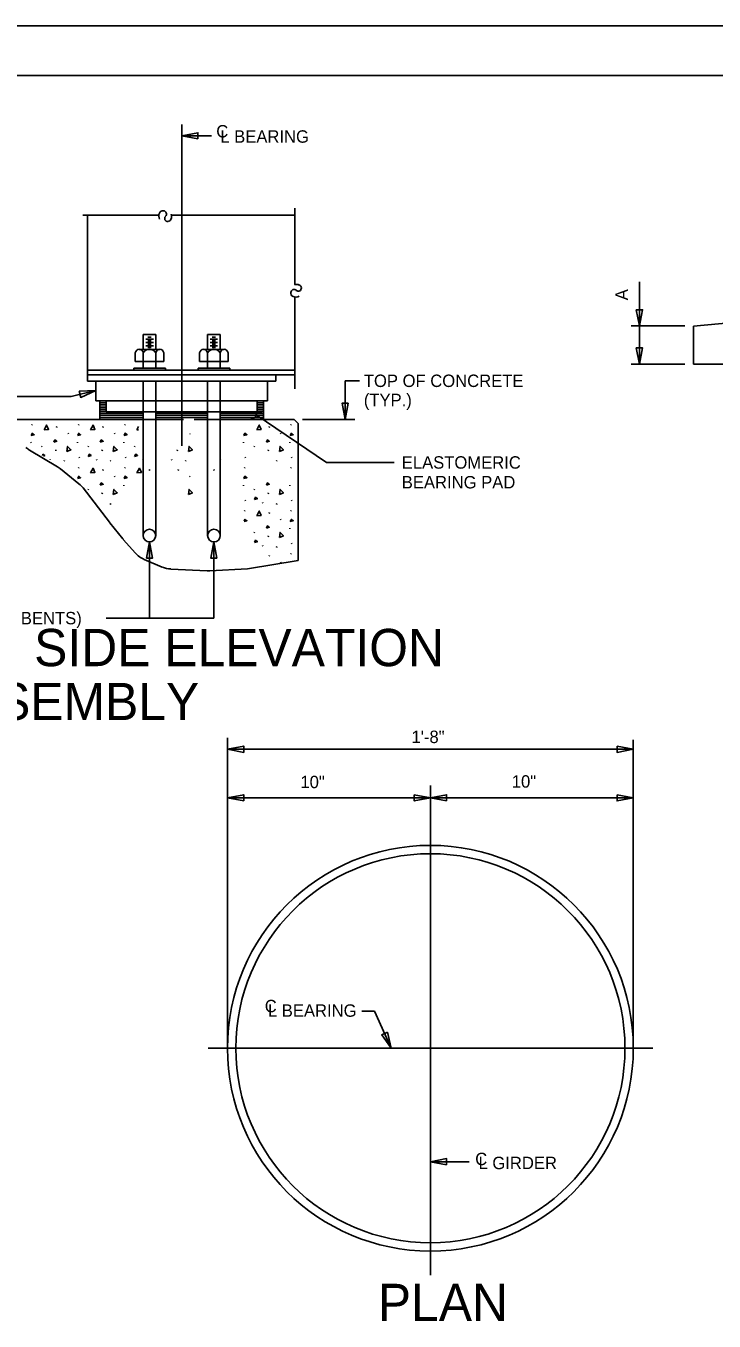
# Model space of a CAD drawing. Extents: x -125.5 to -89.4, y -5.1 to 16.9.
# Drawn here: x -112.46 to -105.53, y 3.9 to 16.93 of the extents above; entities that cross this region are included whole.
import ezdxf

# ---------------------------------------------------------------- set-up
doc = ezdxf.new("R2010")
doc.units = 0
for name, color, linetype in [('BR_AUTO DIMENSION', 7, 'Continuous'), ('BR_BORDER LINES', 7, 'Continuous'), ('BR_CENTER LINES', 7, 'Continuous'), ('BR_CONCRETE', 7, 'Continuous'), ('BR_REBAR', 7, 'Continuous'), ('BR_STRUCTURAL STEEL', 7, 'Continuous'), ('BR_TEXT', 7, 'Continuous'), ('Default', 7, 'Continuous'), ('Level 31', 7, 'Continuous')]:
    doc.layers.add(name, color=color, linetype=linetype)

msp = doc.modelspace()

# ---------------------------------------------------------------- linework, layer by layer
at = {"layer": 'BR_AUTO DIMENSION'}
for p, q in [((-110.889, 15.827), (-110.588, 15.827)), ((-106.282, 13.53), (-106.282, 14.357)), ((-106.365, 13.914), (-105.826, 13.914)), ((-106.365, 13.53), (-105.826, 13.53)), ((-109.244, 12.973), (-109.244, 13.36)), ((-109.244, 13.36), (-109.1, 13.36)), ((-112.001, 13.204), (-112.841, 13.204)), ((-111.755, 13.264), (-112.001, 13.204)), ((-110.139, 13.018), (-109.432, 12.538)), ((-109.674, 12.973), (-109.147, 12.973)), ((-109.432, 12.538), (-108.749, 12.538)), ((-111.213, 11.74), (-111.213, 10.973)), ((-110.565, 11.74), (-110.565, 10.973)), ((-110.565, 10.973), (-111.648, 10.973)), ((-110.428, 7.085), (-110.428, 9.766)), ((-110.428, 9.653), (-106.344, 9.653)), ((-106.344, 7.085), (-106.344, 9.749)), ((-110.428, 9.163), (-106.344, 9.163)), ((-110.428, 6.643), (-110.428, 8.478)), ((-106.344, 6.643), (-106.344, 8.478)), ((-109.075, 7.015), (-108.949, 7.015)), ((-108.949, 7.015), (-108.78, 6.643)), ((-108.386, 5.501), (-107.996, 5.501))]:
    msp.add_line(p, q, dxfattribs=at)
for points in [[(-110.726, 15.796), (-110.889, 15.827), (-110.726, 15.858)], [(-106.314, 14.077), (-106.282, 13.914), (-106.251, 14.077)], [(-106.314, 13.693), (-106.282, 13.53), (-106.251, 13.693)], [(-111.919, 13.256), (-111.754, 13.264), (-111.905, 13.195)], [(-109.213, 13.135), (-109.244, 12.973), (-109.275, 13.135)], [(-111.244, 11.577), (-111.213, 11.739), (-111.181, 11.577)], [(-110.534, 11.577), (-110.565, 11.739), (-110.596, 11.577)], [(-110.265, 9.621), (-110.428, 9.653), (-110.265, 9.684)], [(-106.507, 9.684), (-106.344, 9.653), (-106.507, 9.621)], [(-110.265, 9.132), (-110.428, 9.163), (-110.265, 9.194)], [(-108.549, 9.194), (-108.386, 9.163), (-108.549, 9.132)], [(-108.224, 9.132), (-108.386, 9.163), (-108.224, 9.194)], [(-106.507, 9.194), (-106.344, 9.163), (-106.507, 9.132)], [(-108.819, 6.804), (-108.78, 6.643), (-108.876, 6.778)], [(-108.224, 5.47), (-108.386, 5.501), (-108.224, 5.532)]]:
    msp.add_lwpolyline(points, close=True, dxfattribs=at)
for centre, start, end in [((-110.103, 13.015), 53.0627, 175.5269), ((-110.176, 13.021), 233.0627, 355.5269)]:
    msp.add_arc(centre, 0.0366, start, end, dxfattribs=at)
at = {"layer": 'BR_BORDER LINES'}
msp.add_line((-90.033, 16.434), (-123.699, 16.434), dxfattribs=at)
at = {"layer": 'BR_CENTER LINES'}
for p, q in [((-110.889, 15.941), (-110.889, 12.708)), ((-108.386, 4.359), (-108.386, 9.288)), ((-110.622, 6.643), (-106.147, 6.643))]:
    msp.add_line(p, q, dxfattribs=at)
at = {"layer": 'BR_CONCRETE'}
for p, q in [((-110.915, 12.973), (-112.775, 12.973)), ((-111.629, 12.973), (-110.871, 12.973)), ((-109.758, 12.973), (-110.762, 12.973)), ((-109.758, 12.973), (-109.716, 12.931)), ((-109.716, 11.551), (-109.716, 12.931))]:
    msp.add_line(p, q, dxfattribs=at)
at = {"layer": 'BR_REBAR'}
for p, q in [((-111.276, 13.827), (-111.149, 13.827)), ((-111.276, 13.678), (-111.276, 13.827)), ((-111.149, 13.678), (-111.149, 13.827)), ((-110.502, 13.827), (-110.629, 13.827)), ((-110.629, 13.678), (-110.629, 13.827)), ((-110.502, 13.678), (-110.502, 13.827)), ((-111.251, 13.782), (-111.174, 13.782)), ((-111.251, 13.748), (-111.174, 13.748)), ((-111.251, 13.713), (-111.174, 13.713)), ((-111.229, 13.8), (-111.197, 13.8)), ((-111.229, 13.765), (-111.197, 13.765)), ((-111.229, 13.73), (-111.197, 13.73)), ((-111.229, 13.696), (-111.197, 13.696)), ((-110.527, 13.782), (-110.603, 13.782)), ((-110.527, 13.748), (-110.603, 13.748)), ((-110.527, 13.713), (-110.603, 13.713)), ((-110.549, 13.8), (-110.581, 13.8)), ((-110.549, 13.765), (-110.581, 13.765)), ((-110.549, 13.73), (-110.581, 13.73)), ((-110.549, 13.696), (-110.581, 13.696)), ((-111.356, 13.644), (-111.356, 13.557)), ((-111.316, 13.678), (-111.109, 13.678)), ((-111.276, 13.488), (-111.276, 13.644)), ((-111.149, 13.488), (-111.149, 13.644)), ((-111.069, 13.644), (-111.069, 13.557)), ((-110.709, 13.644), (-110.709, 13.557)), ((-110.462, 13.678), (-110.669, 13.678)), ((-110.629, 13.488), (-110.629, 13.644)), ((-110.502, 13.488), (-110.502, 13.644)), ((-110.422, 13.644), (-110.422, 13.557)), ((-111.372, 13.488), (-111.372, 13.47)), ((-111.372, 13.488), (-111.053, 13.488)), ((-111.069, 13.557), (-111.356, 13.557)), ((-111.053, 13.488), (-111.053, 13.47)), ((-110.724, 13.488), (-110.724, 13.47)), ((-110.406, 13.488), (-110.724, 13.488)), ((-110.709, 13.557), (-110.422, 13.557)), ((-110.406, 13.488), (-110.406, 13.47)), ((-111.276, 13.15), (-111.276, 13.358)), ((-111.149, 13.15), (-111.149, 13.358)), ((-110.629, 13.15), (-110.629, 13.358)), ((-110.502, 13.15), (-110.502, 13.358)), ((-111.276, 12.962), (-111.276, 13.16)), ((-111.149, 12.962), (-111.149, 13.16)), ((-110.629, 12.962), (-110.629, 13.16)), ((-110.502, 12.962), (-110.502, 13.16)), ((-111.276, 11.804), (-111.276, 12.962)), ((-111.149, 11.804), (-111.149, 12.962)), ((-110.629, 11.804), (-110.629, 12.962)), ((-110.502, 11.804), (-110.502, 12.962))]:
    msp.add_line(p, q, dxfattribs=at)
for centre in [(-111.213, 11.804), (-110.565, 11.804)]:
    msp.add_circle(centre, 0.0637, dxfattribs=at)
for centre, major_axis, start_param, end_param in [((-111.316, 13.634), (0, 0.0444), 4.933703, 7.632667), ((-111.213, 13.592), (0, 0.0867), 5.35589, 7.210481), ((-111.109, 13.634), (0, 0.0444), 4.933703, 7.632667), ((-110.669, 13.634), (0, 0.0444), 4.933703, 7.632667), ((-110.565, 13.592), (0, 0.0867), 5.35589, 7.210481), ((-110.462, 13.634), (0, 0.0444), 4.933703, 7.632667)]:
    msp.add_ellipse(centre, major_axis=major_axis, ratio=0.918783, start_param=start_param, end_param=end_param, dxfattribs=at)
at = {"layer": 'BR_STRUCTURAL STEEL'}
for p, q in [((-111.837, 15.028), (-111.837, 13.42)), ((-101.906, 14.291), (-105.739, 13.91)), ((-105.739, 13.91), (-105.739, 13.53)), ((-111.837, 13.47), (-109.75, 13.47)), ((-101.906, 13.53), (-105.739, 13.53)), ((-111.837, 13.42), (-110.588, 13.42)), ((-111.837, 13.42), (-111.837, 13.358)), ((-111.837, 13.358), (-109.941, 13.358)), ((-111.754, 13.358), (-111.754, 13.16)), ((-111.372, 13.358), (-111.053, 13.358)), ((-110.588, 13.42), (-109.75, 13.42)), ((-110.024, 13.358), (-110.024, 13.16)), ((-109.941, 13.42), (-109.941, 13.358)), ((-111.754, 13.16), (-110.024, 13.16)), ((-111.713, 13.16), (-111.713, 12.973)), ((-111.648, 13.049), (-111.648, 13.16)), ((-111.648, 13.049), (-110.13, 13.049)), ((-110.13, 13.049), (-110.13, 13.16)), ((-110.065, 13.16), (-110.065, 12.973))]:
    msp.add_line(p, q, dxfattribs=at)
for radius in [2.042, 1.958]:
    msp.add_circle((-108.386, 6.643), radius, dxfattribs=at)
at = {"layer": 'BR_TEXT'}
for p, q in [((-111.885, 15.028), (-111.119, 15.028)), ((-110.993, 15.028), (-109.75, 15.028)), ((-109.75, 14.331), (-109.75, 15.099)), ((-109.75, 13.282), (-109.75, 14.205))]:
    msp.add_line(p, q, dxfattribs=at)
for centre, radius, start, end in [((-111.049, 15.021), 0.0705, 155.6187, 208.3414), ((-111.077, 15.034), 0.0399, 83.2422, 155.6187), ((-111.076, 15.04), 0.0334, 316.8236, 83.2422), ((-111.03, 14.996), 0.0304, 136.8236, 275.5224), ((-111.061, 15.016), 0.07, 335.6333, 17.6449), ((-111.03, 15.002), 0.0358, 275.5224, 335.6333), ((-109.758, 14.248), 0.0334, 46.8235, 173.2422), ((-109.752, 14.247), 0.0399, 173.2422, 245.6187), ((-109.739, 14.275), 0.0705, 245.6187, 298.3414), ((-109.734, 14.262), 0.07, 65.6333, 107.6449), ((-109.715, 14.294), 0.0304, 226.8236, 5.5224), ((-109.72, 14.294), 0.0358, 5.5224, 65.6333)]:
    msp.add_arc(centre, radius, start, end, dxfattribs=at)
at = {"layer": 'Default'}
for p, q in [((-111.713, 13.139), (-111.648, 13.139)), ((-111.713, 13.118), (-111.648, 13.118)), ((-111.713, 13.097), (-111.648, 13.097)), ((-111.713, 13.077), (-111.648, 13.077)), ((-111.713, 13.056), (-111.648, 13.056)), ((-110.065, 13.139), (-110.13, 13.139)), ((-110.065, 13.118), (-110.13, 13.118)), ((-110.065, 13.097), (-110.13, 13.097)), ((-110.065, 13.077), (-110.13, 13.077)), ((-110.065, 13.056), (-110.13, 13.056)), ((-112.396, 12.914), (-112.392, 12.923)), ((-111.929, 12.914), (-111.925, 12.923)), ((-111.713, 13.035), (-111.276, 13.035)), ((-111.713, 13.014), (-111.276, 13.014)), ((-111.713, 12.993), (-111.276, 12.993)), ((-111.462, 12.914), (-111.459, 12.923)), ((-111.149, 13.035), (-110.629, 13.035)), ((-111.149, 13.014), (-110.629, 13.014)), ((-111.149, 12.993), (-110.629, 12.993)), ((-110.065, 13.035), (-110.502, 13.035)), ((-110.065, 13.014), (-110.502, 13.014)), ((-110.065, 12.993), (-110.502, 12.993)), ((-109.79, 12.914), (-109.786, 12.923)), ((-112.148, 12.893), (-112.144, 12.901)), ((-112.032, 12.834), (-112.029, 12.828)), ((-111.681, 12.893), (-111.678, 12.901)), ((-111.566, 12.834), (-111.562, 12.828)), ((-110.806, 12.829), (-110.805, 12.828)), ((-110.009, 12.893), (-110.005, 12.901)), ((-109.893, 12.834), (-109.89, 12.828)), ((-112.42, 12.664), (-112.137, 12.495)), ((-112.406, 12.745), (-112.405, 12.737)), ((-112.298, 12.696), (-112.294, 12.704)), ((-112.157, 12.658), (-112.154, 12.666)), ((-111.939, 12.745), (-111.938, 12.737)), ((-111.831, 12.696), (-111.828, 12.704)), ((-111.691, 12.658), (-111.687, 12.666)), ((-111.472, 12.745), (-111.471, 12.737)), ((-111.365, 12.696), (-111.361, 12.704)), ((-110.934, 12.658), (-110.93, 12.666)), ((-110.267, 12.745), (-110.266, 12.737)), ((-110.159, 12.696), (-110.155, 12.704)), ((-110.018, 12.658), (-110.015, 12.666)), ((-109.8, 12.745), (-109.799, 12.737)), ((-112.214, 12.569), (-112.212, 12.566)), ((-112.073, 12.551), (-112.069, 12.559)), ((-111.922, 12.592), (-111.918, 12.587)), ((-111.747, 12.569), (-111.744, 12.563)), ((-111.607, 12.551), (-111.603, 12.559)), ((-111.455, 12.592), (-111.451, 12.587)), ((-111.281, 12.569), (-111.277, 12.563)), ((-110.991, 12.569), (-110.987, 12.563)), ((-110.85, 12.551), (-110.846, 12.559)), ((-110.497, 12.569), (-110.501, 12.563)), ((-110.25, 12.592), (-110.246, 12.587)), ((-109.934, 12.551), (-109.93, 12.559)), ((-109.783, 12.592), (-109.779, 12.587)), ((-112.108, 12.475), (-111.923, 12.324)), ((-111.929, 12.482), (-111.925, 12.49)), ((-111.681, 12.46), (-111.678, 12.469)), ((-111.566, 12.401), (-111.562, 12.395)), ((-111.462, 12.482), (-111.459, 12.49)), ((-111.215, 12.46), (-111.211, 12.469)), ((-110.925, 12.46), (-110.921, 12.469)), ((-110.809, 12.401), (-110.805, 12.395)), ((-110.563, 12.46), (-110.567, 12.469)), ((-110.257, 12.482), (-110.253, 12.49)), ((-109.79, 12.482), (-109.786, 12.49)), ((-111.882, 12.283), (-111.616, 11.938)), ((-111.831, 12.264), (-111.828, 12.272)), ((-111.472, 12.312), (-111.471, 12.304)), ((-110.267, 12.312), (-110.266, 12.304)), ((-110.159, 12.263), (-110.155, 12.272)), ((-109.8, 12.312), (-109.799, 12.304)), ((-111.691, 12.225), (-111.687, 12.234)), ((-111.607, 12.118), (-111.603, 12.126)), ((-110.25, 12.16), (-110.246, 12.154)), ((-110.075, 12.136), (-110.071, 12.131)), ((-110.018, 12.225), (-110.015, 12.234)), ((-109.934, 12.118), (-109.93, 12.126)), ((-109.783, 12.16), (-109.779, 12.154)), ((-110.257, 12.049), (-110.253, 12.057)), ((-110.009, 12.027), (-110.005, 12.036)), ((-109.79, 12.049), (-109.786, 12.057)), ((-111.612, 11.933), (-111.48, 11.77)), ((-109.893, 11.968), (-109.89, 11.963)), ((-109.8, 11.879), (-109.799, 11.871)), ((-111.473, 11.762), (-111.356, 11.629)), ((-110.159, 11.83), (-110.155, 11.839)), ((-110.018, 11.792), (-110.015, 11.801)), ((-110.075, 11.703), (-110.071, 11.698)), ((-109.934, 11.685), (-109.93, 11.693)), ((-109.79, 11.616), (-109.786, 11.624)), ((-109.783, 11.727), (-109.779, 11.721)), ((-111.266, 11.564), (-111.084, 11.487)), ((-110.009, 11.595), (-110.005, 11.603)), ((-109.893, 11.535), (-109.89, 11.53)), ((-110.999, 11.467), (-110.633, 11.449))]:
    msp.add_line(p, q, dxfattribs=at)
for points in [[(-112.273, 12.868), (-112.248, 12.915), (-112.229, 12.872), (-112.272, 12.868)], [(-111.806, 12.868), (-111.781, 12.915), (-111.762, 12.872), (-111.805, 12.868)], [(-110.134, 12.868), (-110.109, 12.915), (-110.09, 12.872), (-110.133, 12.868)], [(-112.402, 12.81), (-112.391, 12.833), (-112.372, 12.819), (-112.402, 12.81)], [(-111.935, 12.81), (-111.924, 12.833), (-111.906, 12.819), (-111.935, 12.81)], [(-111.469, 12.81), (-111.458, 12.833), (-111.439, 12.819), (-111.469, 12.81)], [(-111.34, 12.868), (-111.322, 12.901)], [(-111.324, 12.869), (-111.339, 12.868)], [(-110.263, 12.81), (-110.252, 12.833), (-110.233, 12.819), (-110.263, 12.81)], [(-109.796, 12.81), (-109.785, 12.833), (-109.767, 12.819), (-109.796, 12.81)], [(-112.176, 12.744), (-112.165, 12.767), (-112.146, 12.753), (-112.176, 12.744)], [(-112.045, 12.649), (-112.037, 12.701), (-112.004, 12.667), (-112.044, 12.649)], [(-111.709, 12.744), (-111.698, 12.767), (-111.679, 12.753), (-111.709, 12.744)], [(-111.578, 12.649), (-111.571, 12.701), (-111.538, 12.667), (-111.577, 12.649)], [(-110.821, 12.649), (-110.814, 12.701), (-110.781, 12.667), (-110.821, 12.649)], [(-110.037, 12.744), (-110.026, 12.767), (-110.007, 12.753), (-110.037, 12.744)], [(-109.906, 12.649), (-109.898, 12.701), (-109.865, 12.667), (-109.905, 12.649)], [(-112.291, 12.609), (-112.285, 12.622), (-112.267, 12.608), (-112.281, 12.604)], [(-111.829, 12.599), (-111.818, 12.622), (-111.8, 12.608), (-111.829, 12.599)], [(-111.363, 12.599), (-111.352, 12.622), (-111.333, 12.608), (-111.363, 12.599)], [(-111.935, 12.377), (-111.924, 12.4), (-111.906, 12.386), (-111.935, 12.377)], [(-111.806, 12.435), (-111.781, 12.482), (-111.762, 12.439), (-111.805, 12.435)], [(-111.469, 12.377), (-111.458, 12.4), (-111.439, 12.386), (-111.469, 12.377)], [(-111.34, 12.435), (-111.315, 12.482), (-111.295, 12.439), (-111.339, 12.435)], [(-110.263, 12.377), (-110.252, 12.4), (-110.233, 12.386), (-110.263, 12.377)], [(-111.709, 12.311), (-111.698, 12.334), (-111.679, 12.32), (-111.709, 12.311)], [(-111.578, 12.216), (-111.571, 12.269), (-111.538, 12.234), (-111.577, 12.216)], [(-110.821, 12.216), (-110.814, 12.269), (-110.781, 12.234), (-110.821, 12.216)], [(-110.037, 12.311), (-110.026, 12.334), (-110.007, 12.32), (-110.037, 12.311)], [(-109.906, 12.216), (-109.898, 12.269), (-109.865, 12.234), (-109.905, 12.216)], [(-110.157, 12.166), (-110.146, 12.189), (-110.127, 12.175), (-110.157, 12.166)], [(-110.134, 12.002), (-110.109, 12.05), (-110.09, 12.006), (-110.133, 12.002)], [(-110.261, 11.948), (-110.252, 11.967), (-110.233, 11.953), (-110.26, 11.945)], [(-110.037, 11.878), (-110.026, 11.901), (-110.007, 11.887), (-110.037, 11.878)], [(-109.796, 11.944), (-109.785, 11.967), (-109.767, 11.953), (-109.796, 11.944)], [(-110.156, 11.736), (-110.146, 11.756), (-110.127, 11.742), (-110.155, 11.734)], [(-109.906, 11.783), (-109.898, 11.836), (-109.865, 11.802), (-109.905, 11.783)], [(-110.607, 11.449), (-110.228, 11.47), (-109.716, 11.551)]]:
    msp.add_lwpolyline(points, dxfattribs=at)
for centre, start, end in [((-112.291, 12.879), 228.5648, 239.026), ((-112.266, 12.28), 50.9977, 59.026), ((-112.08, 12.13), 37.6364, 50.9977), ((-111.418, 12.09), 217.6364, 219.0825), ((-111.286, 11.928), 219.0825, 221.4122), ((-111.168, 11.794), 221.4122, 247.0596), ((-110.986, 11.717), 247.0596, 267.1364), ((-110.62, 11.699), 267.1364, 273.0953)]:
    msp.add_arc(centre, 0.25, start, end, dxfattribs=at)
at = {"layer": 'Level 31'}
msp.add_line((-89.533, 16.934), (-125.533, 16.934), dxfattribs=at)

# ---------------------------------------------------------------- texts
at = {"layer": 'BR_TEXT'}
for s, height, p in [('C', 0.125, (-110.541, 15.811)), ('L BEARING', 0.125, (-110.5, 15.758)), ('TOP OF CONCRETE', 0.125, (-109.056, 13.299)), ('(TYP.)', 0.125, (-109.056, 13.106)), ('ELASTOMERIC', 0.125, (-108.674, 12.477)), ('BEARING PAD', 0.125, (-108.674, 12.278)), ('1 3/4"   ANCHOR BOLT (ALL BENTS)', 0.125, (-114.731, 10.91)), ('SIDE ELEVATION', 0.375, (-112.374, 10.489)), ('BEARING ASSEMBLY', 0.375, (-115.812, 9.946)), ('1\'-8"', 0.125, (-108.576, 9.715)), ('10"', 0.125, (-109.694, 9.261)), ('10"', 0.125, (-107.567, 9.266)), ('C', 0.125, (-107.935, 5.466)), ('L GIRDER', 0.125, (-107.902, 5.426)), ('PLAN', 0.375, (-108.915, 3.897))]:
    msp.add_text(s, height=height, dxfattribs=at).set_placement(p)
for s, rotation, p in [('A', 90, (-106.399, 14.172)), ('C', 360, (-110.053, 7.005)), ('L BEARING', 360, (-110.021, 6.96))]:
    msp.add_text(s, height=0.125, rotation=rotation, dxfattribs=at).set_placement(p)

doc.saveas('drawing.dxf')
